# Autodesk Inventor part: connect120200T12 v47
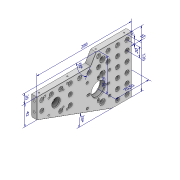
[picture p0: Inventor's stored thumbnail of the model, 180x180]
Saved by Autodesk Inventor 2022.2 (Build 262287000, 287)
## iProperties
Created: 2024-09
Part Number: connect120200T12 v47
Material: 钢
Document SubType Name: Modeling
Designer: 18907419
Density: 7.85 g/cm^3
Appearance: Default
Author: 18907419
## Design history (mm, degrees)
node "Annotazioni"
  node "Quota lineare 1" dims "d2" = 200 (derived), "d5" = 120 (derived)
  node "Quota lineare 2" dims "d5" = 120 (derived)
  node "Quota angolare 1" dims "d5" = 120 (derived), "d10" = 20 deg (derived)
  node "Quota angolare 2" dims "d5" = 120 (derived), "d12" = 60 deg (derived)
  node "Quota lineare 4" dims "d5" = 120 (derived), "d15" = 20 (derived)
  node "Quota lineare 5" dims "d5" = 120 (derived), "d18" = 42 (derived)
  node "Quota lineare 6" dims "d5" = 120 (derived), "d20" = 10 (derived)
  node "Quota lineare 7" dims "d5" = 120 (derived), "d22" = 10 (derived)
  node "Quota lineare 8" dims "d5" = 120 (derived), "d25" = 20 (derived)
  node "Quota lineare 9" dims "d5" = 120 (derived), "d27" = 70.5 (derived)
  node "Quota lineare 10" dims "d5" = 120 (derived), "d29" = 70.25 (derived)
node "Solido1"
node "Solido2"
other parameters: "d0" = 8.16343 (derived), "d1" = 3.43412 (derived), "d11" = 9.61552 (derived), "d13" = 9.38077 (derived), "d14" = 8.04478 (derived), "d16" = 0 (derived), "d19" = 4.14556 (derived), "d21" = 3.96677 (derived), "d23" = 5.73182 (derived), "d24" = 5.75661 (derived), "d26" = 5.89536 (derived), "d28" = 6.1913 (derived), "d3" = 0.89359 (derived), "d4" = 8.10508 (derived), "d8" = 9.84998 (derived), "d9" = 1.18021 (derived)
